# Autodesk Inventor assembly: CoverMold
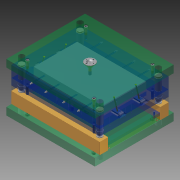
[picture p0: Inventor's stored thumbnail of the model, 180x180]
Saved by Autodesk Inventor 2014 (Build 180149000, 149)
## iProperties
Created: 2009-12
Part Number: CoverMold
Document SubType Name: Assembly
Designer: gaom
Author: gaom
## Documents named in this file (12)
- C:\Users\iTools\Desktop\tutorial files\Mold\CoverMold\Cover Mold\CoverMold.iam
- C:\Users\iTools\Desktop\tutorial files\Mold\CoverMold\Cover Mold\CoverMold_cover_LY.iam
- C:\Users\iTools\Desktop\tutorial files\Mold\CoverMold\Cover Mold\CoverMold_RG.ipt
- C:\Users\iTools\Desktop\tutorial files\Mold\CoverMold\Cover Mold\MB\HASCO_No1 1\CoverMold_MB.iam
- C:\Users\iTools\Desktop\tutorial files\Mold\CoverMold\Cover Mold\CoverMold_Combined CV1.ipt
- C:\Users\iTools\Desktop\tutorial files\Mold\CoverMold\Cover Mold\CoverMold_Combined CR1.ipt
- C:\Users\iTools\Desktop\tutorial files\Mold\CoverMold\Cover Mold\CoverMold_CH.ipt
- C:\Users\iTools\Desktop\tutorial files\Mold\CoverMold\Cover Mold\Cooling Components\DME_AN\CoverMold_AN-4.ipt
- C:\Users\iTools\Desktop\tutorial files\Mold\CoverMold\Cover Mold\Cooling Components\DME_N(N 6-1-8 A SERIE)\CoverMold_N 6-1-4 A.ipt
- C:\Users\iTools\Desktop\tutorial files\Mold\CoverMold\Cover Mold\Cooling Components\DME_DR 1700\CoverMold_DR 1700 10x2.ipt
- C:\Users\iTools\Desktop\tutorial files\Mold\CoverMold\Cover Mold\Sprue Bushing\DME_AG\CoverMold_AG 156-7-0_2.ipt
- C:\Users\iTools\Desktop\tutorial files\Mold\CoverMold\Cover Mold\Locating Ring\DME_DHR 21 - Type C\CoverMold_DHR 21 100-12.ipt
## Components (28 placed, 11 different names)
1. CoverMold_cover_LY:1 [sub-assembly] — Flush:1, Flush:2, Flush:3, Flush:8, Flush:9, Flush:10, Flush:11, Flush:12, Flush:13, Flush:14, Flush:15, Flush:16, Flush:17, Flush:18, Flush:19, Flush:20, Flush:21, Flush:22, Flush:23, Flush:24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
2. CoverMold_RG:1 — Flush:5, Flush:6, Flush:7, Mate:2, Mate:28
3. CoverMold_MB:1 [sub-assembly] — Mate:1, Angle:1, Flush:9, Flush:10, Flush:11, Flush:12, Flush:13, Flush:14, Flush:15, Flush:16, Flush:17, Flush:18, Flush:19, Flush:20, Flush:21, Flush:22, Flush:23, Flush:24, Flush:25, Flush:26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
4. CoverMold_Combined CV1:1 — Flush:115, Flush:116, Flush:117, Insert:3, Insert:4, Insert:5, Insert:6
5. CoverMold_Combined CR1:1 — Flush:118, Flush:119, Flush:120
6. CoverMold_CH:1 — Insert:7, Insert:8, Insert:10, Insert:12, Insert:14
7. AN AN-4:1 — Insert:3
8. AN AN-4:2 — Insert:4
9. AN AN-4:3 — Insert:5
10. AN AN-4:4 — Insert:6
11. N(N 6-1-8 A SERIE) A:1 — Insert:7
12. N(N 6-1-8 A SERIE) A:2 — Insert:8
13. N(N 6-1-8 A SERIE) A:3 — Insert:9
14. N(N 6-1-8 A SERIE) A:4 — Insert:10
15. N(N 6-1-8 A SERIE) A:5 — Insert:11
16. N(N 6-1-8 A SERIE) A:6 — Insert:12
17. N(N 6-1-8 A SERIE) A:7 — Insert:13
18. N(N 6-1-8 A SERIE) A:8 — Insert:14
19. DR 1700 DR 1700 10x2:1
20. DR 1700 DR 1700 10x2:2
21. DR 1700 DR 1700 10x2:3
22. DR 1700 DR 1700 10x2:4
23. DR 1700 DR 1700 10x2:5
24. DR 1700 DR 1700 10x2:6
25. DR 1700 DR 1700 10x2:7
26. DR 1700 DR 1700 10x2:8
27. CoverMold_AG 156-7-0_2:1 — Mate:27, Mate:28, Mate:30
28. CoverMold_DHR 21 100-12:1 — Mate:29, Mate:30
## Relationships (149: Flush 118, Mate 18, Insert 12, Angle 1)
- Flush:1: CoverMold_cover_LY:1
- Flush:2: CoverMold_cover_LY:1
- Flush:3: CoverMold_cover_LY:1
- Mate:1: CoverMold_MB:1
- Angle:1: CoverMold_MB:1
- Flush:5: CoverMold_RG:1
- Flush:6: CoverMold_RG:1
- Flush:7: CoverMold_RG:1
- Flush:8: CoverMold_cover_LY:1
- Mate:2: CoverMold_RG:1
- Flush:9: CoverMold_cover_LY:1 ↔ CoverMold_MB:1
- Flush:10: CoverMold_cover_LY:1 ↔ CoverMold_MB:1
- Flush:11: CoverMold_cover_LY:1 ↔ CoverMold_MB:1
- Flush:12: CoverMold_cover_LY:1 ↔ CoverMold_MB:1
- Flush:13: CoverMold_cover_LY:1 ↔ CoverMold_MB:1
- Flush:14: CoverMold_cover_LY:1 ↔ CoverMold_MB:1
- Flush:15: CoverMold_cover_LY:1 ↔ CoverMold_MB:1
- Flush:16: CoverMold_cover_LY:1 ↔ CoverMold_MB:1
- Flush:17: CoverMold_cover_LY:1 ↔ CoverMold_MB:1
- Flush:18: CoverMold_cover_LY:1 ↔ CoverMold_MB:1
- Flush:19: CoverMold_cover_LY:1 ↔ CoverMold_MB:1
- Flush:20: CoverMold_cover_LY:1 ↔ CoverMold_MB:1
- Flush:21: CoverMold_cover_LY:1 ↔ CoverMold_MB:1
- Flush:22: CoverMold_cover_LY:1 ↔ CoverMold_MB:1
- Flush:23: CoverMold_cover_LY:1 ↔ CoverMold_MB:1
- Flush:24: CoverMold_cover_LY:1 ↔ CoverMold_MB:1
- Flush:25: CoverMold_cover_LY:1 ↔ CoverMold_MB:1
- Flush:26: CoverMold_cover_LY:1 ↔ CoverMold_MB:1
- Flush:27: CoverMold_cover_LY:1 ↔ CoverMold_MB:1
- Flush:28: CoverMold_cover_LY:1 ↔ CoverMold_MB:1
- Flush:29: CoverMold_cover_LY:1 ↔ CoverMold_MB:1
- Flush:30: CoverMold_cover_LY:1 ↔ CoverMold_MB:1
- Flush:31: CoverMold_cover_LY:1 ↔ CoverMold_MB:1
- Flush:32: CoverMold_cover_LY:1 ↔ CoverMold_MB:1
- Flush:33: CoverMold_cover_LY:1 ↔ CoverMold_MB:1
- Flush:34: CoverMold_cover_LY:1 ↔ CoverMold_MB:1
- Flush:35: CoverMold_cover_LY:1 ↔ CoverMold_MB:1
- Flush:36: CoverMold_cover_LY:1 ↔ CoverMold_MB:1
- Flush:37: CoverMold_cover_LY:1 ↔ CoverMold_MB:1
- Flush:38: CoverMold_cover_LY:1 ↔ CoverMold_MB:1
- Flush:39: CoverMold_cover_LY:1 ↔ CoverMold_MB:1
- Flush:40: CoverMold_cover_LY:1 ↔ CoverMold_MB:1
- Flush:41: CoverMold_cover_LY:1 ↔ CoverMold_MB:1
- Flush:42: CoverMold_cover_LY:1 ↔ CoverMold_MB:1
- Flush:43: CoverMold_cover_LY:1 ↔ CoverMold_MB:1
- Flush:44: CoverMold_cover_LY:1 ↔ CoverMold_MB:1
- Flush:45: CoverMold_cover_LY:1 ↔ CoverMold_MB:1
- Flush:46: CoverMold_cover_LY:1 ↔ CoverMold_MB:1
- Flush:47: CoverMold_cover_LY:1 ↔ CoverMold_MB:1
- Flush:48: CoverMold_cover_LY:1 ↔ CoverMold_MB:1
- Flush:49: CoverMold_cover_LY:1 ↔ CoverMold_MB:1
- Flush:50: CoverMold_cover_LY:1 ↔ CoverMold_MB:1
- Flush:51: CoverMold_cover_LY:1 ↔ CoverMold_MB:1
- Flush:52: CoverMold_cover_LY:1 ↔ CoverMold_MB:1
- Flush:53: CoverMold_cover_LY:1 ↔ CoverMold_MB:1
- Flush:54: CoverMold_cover_LY:1 ↔ CoverMold_MB:1
- Flush:55: CoverMold_cover_LY:1 ↔ CoverMold_MB:1
- Flush:56: CoverMold_cover_LY:1 ↔ CoverMold_MB:1
- Flush:57: CoverMold_cover_LY:1 ↔ CoverMold_MB:1
- Flush:58: CoverMold_cover_LY:1 ↔ CoverMold_MB:1
- Flush:59: CoverMold_cover_LY:1 ↔ CoverMold_MB:1
- Flush:60: CoverMold_cover_LY:1 ↔ CoverMold_MB:1
- Flush:61: CoverMold_cover_LY:1 ↔ CoverMold_MB:1
- Flush:62: CoverMold_cover_LY:1 ↔ CoverMold_MB:1
- Flush:63: CoverMold_cover_LY:1 ↔ CoverMold_MB:1
- Flush:64: CoverMold_cover_LY:1 ↔ CoverMold_MB:1
- Flush:65: CoverMold_cover_LY:1 ↔ CoverMold_MB:1
- Flush:66: CoverMold_cover_LY:1 ↔ CoverMold_MB:1
- Flush:67: CoverMold_cover_LY:1 ↔ CoverMold_MB:1
- Flush:68: CoverMold_cover_LY:1 ↔ CoverMold_MB:1
- Flush:69: CoverMold_cover_LY:1 ↔ CoverMold_MB:1
- Flush:70: CoverMold_cover_LY:1 ↔ CoverMold_MB:1
- Flush:71: CoverMold_cover_LY:1 ↔ CoverMold_MB:1
- Flush:72: CoverMold_cover_LY:1 ↔ CoverMold_MB:1
- Flush:73: CoverMold_cover_LY:1 ↔ CoverMold_MB:1
- Flush:74: CoverMold_cover_LY:1 ↔ CoverMold_MB:1
- Flush:75: CoverMold_cover_LY:1 ↔ CoverMold_MB:1
- Flush:76: CoverMold_cover_LY:1 ↔ CoverMold_MB:1
- Flush:77: CoverMold_cover_LY:1 ↔ CoverMold_MB:1
- Flush:78: CoverMold_cover_LY:1 ↔ CoverMold_MB:1
- Flush:79: CoverMold_cover_LY:1 ↔ CoverMold_MB:1
- Flush:80: CoverMold_cover_LY:1 ↔ CoverMold_MB:1
- Flush:81: CoverMold_cover_LY:1 ↔ CoverMold_MB:1
- Flush:82: CoverMold_cover_LY:1 ↔ CoverMold_MB:1
- Mate:3: CoverMold_cover_LY:1 ↔ CoverMold_MB:1
- Flush:83: CoverMold_cover_LY:1 ↔ CoverMold_MB:1
- Flush:84: CoverMold_cover_LY:1 ↔ CoverMold_MB:1
- Flush:85: CoverMold_cover_LY:1 ↔ CoverMold_MB:1
- Mate:4: CoverMold_cover_LY:1 ↔ CoverMold_MB:1
- Flush:86: CoverMold_cover_LY:1 ↔ CoverMold_MB:1
- Flush:87: CoverMold_cover_LY:1 ↔ CoverMold_MB:1
- Flush:88: CoverMold_cover_LY:1 ↔ CoverMold_MB:1
- Mate:5: CoverMold_cover_LY:1 ↔ CoverMold_MB:1
- Flush:89: CoverMold_cover_LY:1 ↔ CoverMold_MB:1
- Flush:90: CoverMold_cover_LY:1 ↔ CoverMold_MB:1
- Flush:91: CoverMold_cover_LY:1 ↔ CoverMold_MB:1
- Mate:6: CoverMold_cover_LY:1 ↔ CoverMold_MB:1
- Flush:92: CoverMold_cover_LY:1 ↔ CoverMold_MB:1
- Mate:7: CoverMold_cover_LY:1 ↔ CoverMold_MB:1
- Flush:93: CoverMold_cover_LY:1 ↔ CoverMold_MB:1
- Flush:94: CoverMold_cover_LY:1 ↔ CoverMold_MB:1
- Mate:8: CoverMold_cover_LY:1 ↔ CoverMold_MB:1
- Flush:95: CoverMold_cover_LY:1 ↔ CoverMold_MB:1
- Flush:96: CoverMold_cover_LY:1 ↔ CoverMold_MB:1
- Mate:9: CoverMold_cover_LY:1 ↔ CoverMold_MB:1
- Flush:97: CoverMold_cover_LY:1 ↔ CoverMold_MB:1
- Flush:98: CoverMold_cover_LY:1 ↔ CoverMold_MB:1
- Mate:10: CoverMold_cover_LY:1 ↔ CoverMold_MB:1
- Flush:99: CoverMold_cover_LY:1 ↔ CoverMold_MB:1
- Flush:100: CoverMold_cover_LY:1 ↔ CoverMold_MB:1
- Flush:102: CoverMold_cover_LY:1 ↔ CoverMold_MB:1
- Flush:103: CoverMold_cover_LY:1 ↔ CoverMold_MB:1
- Mate:15: CoverMold_cover_LY:1 ↔ CoverMold_MB:1
- Flush:104: CoverMold_cover_LY:1 ↔ CoverMold_MB:1
- Flush:105: CoverMold_cover_LY:1 ↔ CoverMold_MB:1
- Mate:16: CoverMold_cover_LY:1 ↔ CoverMold_MB:1
- Flush:106: CoverMold_cover_LY:1 ↔ CoverMold_MB:1
- Flush:107: CoverMold_cover_LY:1 ↔ CoverMold_MB:1
- Mate:17: CoverMold_cover_LY:1 ↔ CoverMold_MB:1
- Flush:108: CoverMold_cover_LY:1 ↔ CoverMold_MB:1
- Flush:109: CoverMold_cover_LY:1 ↔ CoverMold_MB:1
- Mate:18: CoverMold_cover_LY:1 ↔ CoverMold_MB:1
- Flush:110: CoverMold_cover_LY:1 ↔ CoverMold_MB:1
- Flush:111: CoverMold_cover_LY:1 ↔ CoverMold_MB:1
- Flush:112: CoverMold_cover_LY:1 ↔ CoverMold_MB:1
- Flush:113: CoverMold_cover_LY:1 ↔ CoverMold_MB:1
- Flush:114: CoverMold_cover_LY:1 ↔ CoverMold_MB:1
- Flush:115: CoverMold_Combined CV1:1
- Flush:116: CoverMold_Combined CV1:1
- Flush:117: CoverMold_Combined CV1:1
- Flush:118: CoverMold_Combined CR1:1
- Flush:119: CoverMold_Combined CR1:1
- Flush:120: CoverMold_Combined CR1:1
- Insert:3: CoverMold_Combined CV1:1 ↔ AN AN-4:1
- Insert:4: CoverMold_Combined CV1:1 ↔ AN AN-4:2
- Insert:5: CoverMold_Combined CV1:1 ↔ AN AN-4:3
- Insert:6: CoverMold_Combined CV1:1 ↔ AN AN-4:4
- Insert:7: CoverMold_CH:1 ↔ N(N 6-1-8 A SERIE) A:1
- Insert:8: CoverMold_CH:1 ↔ N(N 6-1-8 A SERIE) A:2
- Insert:9: CoverMold_MB:1 ↔ N(N 6-1-8 A SERIE) A:3
- Insert:10: CoverMold_CH:1 ↔ N(N 6-1-8 A SERIE) A:4
- Insert:11: CoverMold_MB:1 ↔ N(N 6-1-8 A SERIE) A:5
- Insert:12: CoverMold_CH:1 ↔ N(N 6-1-8 A SERIE) A:6
- Insert:13: CoverMold_MB:1 ↔ N(N 6-1-8 A SERIE) A:7
- Insert:14: CoverMold_CH:1 ↔ N(N 6-1-8 A SERIE) A:8
- Mate:27: CoverMold_MB:1 ↔ CoverMold_AG 156-7-0_2:1
- Mate:28: CoverMold_RG:1 ↔ CoverMold_AG 156-7-0_2:1
- Mate:29: CoverMold_MB:1 ↔ CoverMold_DHR 21 100-12:1
- Mate:30: CoverMold_AG 156-7-0_2:1 ↔ CoverMold_DHR 21 100-12:1
